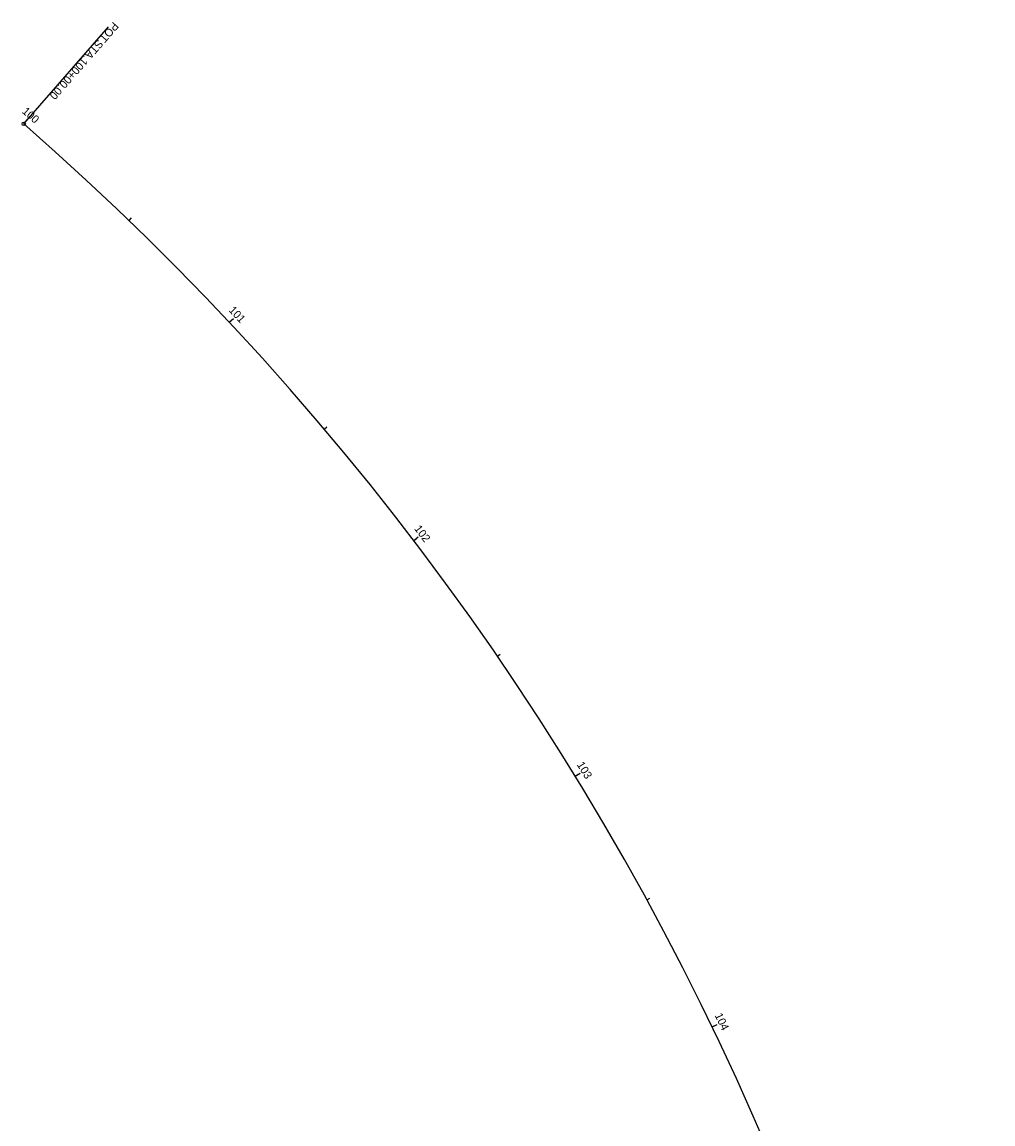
# Model space of a CAD drawing. Extents: x 1392427 to 1392809, y 435950 to 439080.
# Drawn here: x 1392427 to 1392766.7, y 438694.9 to 439080.4 of the extents above; entities that cross this region are included whole.
import ezdxf

# ---------------------------------------------------------------- set-up
doc = ezdxf.new("R2010")
doc.units = 0
for name, color, linetype in [('Default', 7, 'Continuous'), ('PV_X_Curb', 7, 'Continuous'), ('RD_X_Cells', 7, 'Continuous'), ('RW_X_CL', 7, 'Continuous'), ('RW_X_CL_100_Stations', 7, 'Continuous'), ('SV_X_Mon_Cells_Found', 7, 'Continuous'), ('VG_X_Shrub_Line_Lt', 7, 'Continuous')]:
    doc.layers.add(name, color=color, linetype=linetype)

msp = doc.modelspace()

# ---------------------------------------------------------------- linework, layer by layer
at = {"layer": 'Default'}
msp.add_arc((1391776.54, 438298.83), 990.19, 355.29887, 48.88602, dxfattribs=at)
at = {"layer": 'PV_X_Curb'}
for p, q in [((1392427.65, 439044.84), (1392428.96, 439046.35)), ((1392499.54, 438975.4), (1392500.42, 438976.22)), ((1392564.07, 438899.06), (1392565.03, 438899.78)), ((1392620.57, 438816.6), (1392621.6, 438817.23)), ((1392668.47, 438728.87), (1392669.55, 438729.39))]:
    msp.add_line(p, q, dxfattribs=at)
at = {"layer": 'RD_X_Cells'}
msp.add_line((1392427.65, 439044.84), (1392428.96, 439046.35), dxfattribs=at)
at = {"layer": 'RW_X_CL'}
msp.add_arc((1391776.54, 438298.83), 990.19, 355.29887, 48.88602, dxfattribs=at)
msp.add_arc((1391776.54, 438298.83), 990.19, 355.29887, 48.88602, dxfattribs=at)
at = {"layer": 'RW_X_CL_100_Stations'}
for p, q in [((1392427.65, 439044.84), (1392428.96, 439046.35)), ((1392464.47, 439011.03), (1392465.31, 439011.89)), ((1392499.54, 438975.4), (1392501, 438976.76)), ((1392532.77, 438938.04), (1392533.69, 438938.82)), ((1392564.07, 438899.06), (1392565.66, 438900.27)), ((1392593.36, 438858.54), (1392594.35, 438859.22)), ((1392620.57, 438816.6), (1392622.28, 438817.65)), ((1392645.63, 438773.34), (1392646.68, 438773.91)), ((1392668.47, 438728.87), (1392670.28, 438729.74))]:
    msp.add_line(p, q, dxfattribs=at)
at = {"layer": 'SV_X_Mon_Cells_Found'}
for p, q in [((1392427.65, 439044.84), (1392428.96, 439046.35)), ((1392499.54, 438975.4), (1392500.42, 438976.22)), ((1392564.07, 438899.06), (1392565.03, 438899.78)), ((1392620.57, 438816.6), (1392621.6, 438817.23)), ((1392668.47, 438728.87), (1392669.55, 438729.39))]:
    msp.add_line(p, q, dxfattribs=at)
at = {"layer": 'VG_X_Shrub_Line_Lt'}
msp.add_line((1392427.65, 439044.84), (1392457.24, 439078.74), dxfattribs=at)
msp.add_circle((1392427.65, 439044.84), 0.6, dxfattribs=at)

# ---------------------------------------------------------------- texts
at = {"layer": 'PV_X_Curb'}
msp.add_text('100', height=2.8, rotation=318.886, dxfattribs=at).set_placement((1392426.83, 439048.87))
at = {"layer": 'RD_X_Cells'}
msp.add_text('100', height=2.8, rotation=318.886, dxfattribs=at).set_placement((1392426.83, 439048.87))
at = {"layer": 'RW_X_CL_100_Stations'}
for s, rotation, p in [('100', 318.886, (1392426.83, 439048.87)), ('101', 313.0997, (1392499.17, 438979.46)), ('102', 307.3134, (1392564.11, 438903.13)), ('103', 301.5271, (1392621.03, 438820.63)), ('104', 295.7408, (1392669.3, 438732.91))]:
    msp.add_text(s, height=2.8, rotation=rotation, dxfattribs=at).set_placement(p)
at = {"layer": 'SV_X_Mon_Cells_Found'}
msp.add_text('100', height=2.8, rotation=318.886, dxfattribs=at).set_placement((1392426.83, 439048.87))
at = {"layer": 'VG_X_Shrub_Line_Lt'}
for s, p in [('POT', (1392458.98, 439080.68)), (' STA. ', (1392454.29, 439075.31)), ('100+00.00', (1392448.16, 439068.28))]:
    msp.add_text(s, height=2.8, rotation=228.886, dxfattribs=at).set_placement(p)

doc.saveas('drawing.dxf')
